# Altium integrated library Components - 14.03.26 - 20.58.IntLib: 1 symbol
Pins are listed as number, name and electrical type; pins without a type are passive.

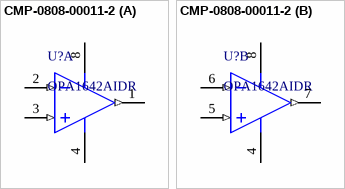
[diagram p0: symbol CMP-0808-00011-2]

## CMP-0808-00011-2
designator U?, comment OPA1642AIDR
Sound-Plus High-Performance, JFET-Input Audio Operational Amplifier, 4.5 to 36 V, -40 to 85 degC, 8-pin SOIC (D8), Green (RoHS & no Sb/Br); Manufacturer: Texas Instruments; Vn at Flatband(Typ)(nV/rtHz): 5.1; Vmin(V): 5; GBW(Typ)(MHz): 11; Number of Channels: 2; Iq per channel(Max)(mA): 2.3; Vmax(V): 36
footprint D0008A_N (SOIC, 8-Leads, Body 5x4mm, Pitch 1.27mm, IPC Medium Density)
footprint D0008A_L (SOIC, 8-Leads, Body 5x4mm, Pitch 1.27mm, IPC High Density)
footprint D0008A_M (SOIC, 8-Leads, Body 5x4mm, Pitch 1.27mm, IPC Low Density)
pins on every part: 4 V- (power), 8 V+ (power)
part A pins: 1 OUT A (out), 2 IN A- (in), 3 IN A+ (in)
part B pins: 5 IN B+ (in), 6 IN B- (in), 7 OUT B (out)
